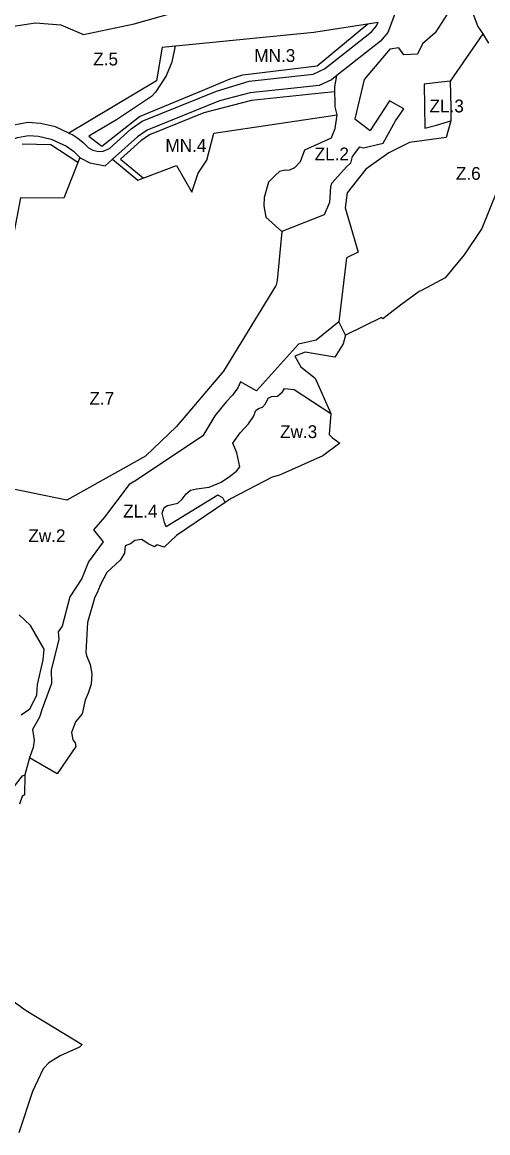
# Model space of a CAD drawing. Extents: x 7425478 to 7427982, y 5538517 to 5541171.
# Drawn here: x 7426780 to 7427144, y 5539848 to 5540715 of the extents above; entities that cross this region are included whole.
import ezdxf

# ---------------------------------------------------------------- set-up
doc = ezdxf.new("R2010")
doc.units = 0
for name, color, linetype in [('linie_rozgraniczajace', 7, 'Continuous'), ('linie_zabudowy_nieprzekraczalne', 7, 'Continuous'), ('oznaczenia_przeznaczen', 7, 'Continuous')]:
    doc.layers.add(name, color=color, linetype=linetype)

msp = doc.modelspace()

# ---------------------------------------------------------------- linework, layer by layer
at = {"layer": 'linie_rozgraniczajace'}
for p, q in [((7427139.8, 5540706.06), (7427114.35, 5540669.29)), ((7426885.22, 5540669.48), (7426816.94, 5540628.58)), ((7426929.93, 5540628.75), (7427026.21, 5540642.98)), ((7426924.55, 5540607.43), (7426929.93, 5540628.75)), ((7426850.92, 5540608.27), (7426845.13, 5540603.14)), ((7426850.92, 5540608.27), (7426870.65, 5540592.04)), ((7426870.65, 5540592.04), (7426900.74, 5540603.34)), ((7427032.6, 5540471.1), (7427027.43, 5540481.44))]:
    msp.add_line(p, q, dxfattribs=at)
for points in [[(7427158.39, 5540798), (7427136.34, 5540789.37), (7427139.67, 5540778.67), (7427134.83, 5540763.31), (7427130.62, 5540745.07), (7427123.48, 5540740.52), (7427119.13, 5540731.95), (7427130.46, 5540726.07), (7427136.02, 5540711.98), (7427139.8, 5540706.06), (7427144.31, 5540698.99)], [(7426717.2, 5540708.68), (7426751.28, 5540708.68), (7426790.92, 5540714.76), (7426810.72, 5540713.06), (7426828.41, 5540705.75), (7426867.84, 5540713.85), (7426908.44, 5540725.51), (7426925.27, 5540731.18), (7426935.28, 5540732.24), (7426974.9, 5540738.42), (7427001.7, 5540742.96), (7427027.17, 5540753.71), (7427042.19, 5540761.09), (7427056.12, 5540769.24), (7427073.04, 5540767.39)], [(7427083.04, 5540766.57), (7427080.34, 5540749.86), (7427070.28, 5540719), (7427065.65, 5540707.16), (7427060.1, 5540700.5), (7427027.21, 5540674.65), (7427025.96, 5540673.63)], [(7427119.13, 5540731.95), (7427118.93, 5540725.92), (7427111.93, 5540721.58), (7427102.54, 5540707.01), (7427092.86, 5540698.44), (7427088.98, 5540690.18), (7427078.3, 5540689.89), (7427074.37, 5540695.25), (7427067.2, 5540694.18), (7427047.31, 5540670.39), (7427040.04, 5540639.71), (7427051.91, 5540630.81)], [(7426816.94, 5540628.58), (7426819.88, 5540627.22), (7426823.81, 5540624.73), (7426827.92, 5540621.26), (7426832.12, 5540617.13), (7426835.64, 5540615.25), (7426839.95, 5540614.22), (7426843.52, 5540614.54), (7426848.64, 5540616.78), (7426865.59, 5540631.91), (7426874, 5540638.01), (7426932, 5540661.5), (7426957.66, 5540669.31), (7427007.45, 5540674.6), (7427016.45, 5540678.79), (7427020.96, 5540682.46), (7427053.09, 5540707.71), (7427056.93, 5540712.31), (7427058.07, 5540715.23)], [(7426889.78, 5540695.66), (7427007.88, 5540707.42), (7427058.07, 5540715.23)], [(7426889.78, 5540695.66), (7426885.22, 5540669.48)], [(7427025.96, 5540673.63), (7427021.8, 5540670.25), (7427012.12, 5540665.74), (7426958.39, 5540660.04), (7426934.51, 5540653.88), (7426877.87, 5540630.95), (7426870.53, 5540625.74), (7426850.92, 5540608.27)], [(7427026.21, 5540642.98), (7427024.52, 5540649.27), (7427024.51, 5540664.71), (7427025.96, 5540673.63)], [(7427114.35, 5540669.29), (7427102.63, 5540667.82), (7427094.19, 5540666.76), (7427094.51, 5540632.57), (7427103.73, 5540634.94), (7427114.78, 5540638.2)], [(7427114.35, 5540669.29), (7427114.9, 5540648.8), (7427114.78, 5540638.2)], [(7427043.54, 5540617.89), (7427046.67, 5540617.1), (7427062.21, 5540620.8), (7427071.76, 5540638.27), (7427078.24, 5540647.6), (7427067.16, 5540653.8), (7427051.91, 5540630.81)], [(7427022.1, 5540625.69), (7427024.7, 5540632.23), (7427026.21, 5540642.98)], [(7427114.78, 5540638.2), (7427111.29, 5540625.32), (7427082.64, 5540621.43), (7427066.46, 5540613.16), (7427048.55, 5540600.64), (7427033.93, 5540581.97), (7427032.56, 5540570.47), (7427042.54, 5540535.68), (7427033.51, 5540531.31), (7427027.43, 5540481.44)], [(7426816.94, 5540628.58), (7426806.42, 5540633.45), (7426794.75, 5540636.3), (7426784.82, 5540636.93), (7426773.93, 5540634.87), (7426749.1, 5540625.08), (7426736.88, 5540615.14)], [(7426539.11, 5540398.25), (7426541.43, 5540399.68), (7426607.94, 5540440.48), (7426649.9, 5540466.22), (7426659.15, 5540471.89), (7426732.05, 5540546.65), (7426737.1, 5540553.97), (7426740.18, 5540562.9), (7426745.32, 5540603.54), (7426750.19, 5540612.79), (7426754.12, 5540616.34), (7426776.71, 5540625.22), (7426785.4, 5540626.76), (7426793.22, 5540626.29), (7426803.14, 5540623.95), (7426814.99, 5540618.47), (7426820.42, 5540614.61), (7426825.48, 5540609.63)], [(7426985.66, 5540599.77), (7426989.18, 5540600.1), (7426993.13, 5540601.91), (7426997.47, 5540606.59), (7427001.04, 5540615.75), (7427021.81, 5540624.97), (7427022.1, 5540625.69)], [(7427043.54, 5540617.89), (7427038, 5540610.44), (7427036.59, 5540605.3), (7427033.74, 5540602.71), (7427021.87, 5540589.27), (7427020.93, 5540586.74), (7427020.23, 5540574.54), (7427015.95, 5540565), (7426983.04, 5540551.77)], [(7426825.48, 5540609.63), (7426812.98, 5540577.96), (7426779.26, 5540578.26), (7426773.48, 5540547.95), (7426764.01, 5540550.84), (7426743.97, 5540499.31)], [(7426825.48, 5540609.63), (7426826.1, 5540609.01), (7426833.3, 5540605.53), (7426845.13, 5540603.14)], [(7426900.74, 5540603.34), (7426912.69, 5540582.71), (7426917.78, 5540597.51), (7426924.55, 5540607.43)], [(7426985.66, 5540599.77), (7426981.3, 5540598.7), (7426977.71, 5540595.7), (7426972.69, 5540590.28), (7426969.22, 5540578.33), (7426969.01, 5540572.04), (7426970.63, 5540563.16), (7426983.04, 5540551.77)], [(7427150.95, 5540583.84), (7427138.96, 5540554.17), (7427125.36, 5540533.58), (7427110.38, 5540515.76), (7427091.99, 5540505.94), (7427090.1, 5540504.94), (7427075.65, 5540494.42), (7427061.83, 5540483.7), (7427060.76, 5540484.77), (7427032.6, 5540471.1), (7427030.76, 5540464.33), (7427024.38, 5540453.77), (7427001.36, 5540457.81), (7426993.3, 5540454.47), (7426997.77, 5540446.18), (7427009.07, 5540437.32), (7427021.32, 5540409.86), (7427020.08, 5540393.37), (7427022.61, 5540390.72), (7427028.34, 5540386.75), (7427015.04, 5540376.71), (7426981.24, 5540361.71), (7426975.61, 5540360.24), (7426943.45, 5540343.38), (7426938.89, 5540340.31), (7426900.87, 5540314.74), (7426891.34, 5540305.49), (7426885.84, 5540307.32), (7426883.78, 5540305.87), (7426878.7, 5540308.24), (7426876.09, 5540309.93), (7426873.47, 5540311.61), (7426868.35, 5540310.69), (7426864.88, 5540308.01), (7426860.83, 5540306.48), (7426860.3, 5540300.95), (7426858.62, 5540298.27), (7426857.01, 5540295.41), (7426846.5, 5540285.63), (7426841.75, 5540276.81), (7426839.37, 5540271.25), (7426836.99, 5540265.69), (7426831.46, 5540246.75), (7426830.08, 5540223.37), (7426830.71, 5540220.99), (7426833.37, 5540213.93), (7426834.71, 5540206.55), (7426834.36, 5540198.53), (7426831.92, 5540191.52), (7426829.64, 5540186.14), (7426827.16, 5540175.36), (7426822.14, 5540169.32), (7426818.84, 5540160.81), (7426819.93, 5540155.13), (7426821.9, 5540152.81), (7426822.39, 5540149.98), (7426807.77, 5540128.74), (7426786.11, 5540141.2), (7426782.46, 5540127.73), (7426782.23, 5540112.34), (7426780.53, 5540110.98), (7426778.31, 5540104.9)], [(7426983.04, 5540551.77), (7426979.38, 5540513.58), (7426978.32, 5540509.52)], [(7426978.32, 5540509.52), (7426978.15, 5540509.1), (7426937.58, 5540442.83), (7426900.97, 5540399.74), (7426876.56, 5540376.66)], [(7427027.43, 5540481.44), (7427009.75, 5540467.1), (7426996.15, 5540464.02), (7426963.33, 5540427.58), (7426950.77, 5540434.53), (7426948.61, 5540429.76), (7426944.61, 5540424.21), (7426939.52, 5540418.88), (7426930.86, 5540407.97), (7426921.46, 5540392.4), (7426869.62, 5540357.86), (7426863.82, 5540354.4), (7426844.64, 5540328.87), (7426836.17, 5540319.03), (7426843.63, 5540309.7), (7426832.11, 5540294.14), (7426827.07, 5540280.94), (7426817.51, 5540266.74), (7426811.68, 5540243.98), (7426808.47, 5540239.34), (7426808.92, 5540233.63), (7426803.14, 5540209.55), (7426803.27, 5540199.17), (7426796, 5540179.23), (7426794.02, 5540172.87), (7426788.54, 5540163.16), (7426789.86, 5540154.88), (7426789.06, 5540149.13), (7426786.11, 5540141.2)], [(7426938.89, 5540340.31), (7426937.09, 5540344.03), (7426933.01, 5540346), (7426892.91, 5540321.35), (7426891.45, 5540324.65), (7426889.79, 5540332.1), (7426891.19, 5540336.41), (7426893.71, 5540337.94), (7426901.86, 5540339.76), (7426905.37, 5540342.93), (7426908.35, 5540347.13), (7426911.75, 5540350.1), (7426916.53, 5540351.01), (7426926.41, 5540352.22), (7426935.65, 5540356.31), (7426942.22, 5540360.57), (7426947.79, 5540364.77), (7426950.29, 5540368.32), (7426947.95, 5540379.04), (7426944.74, 5540386.58), (7426950.54, 5540394.76), (7426957.02, 5540401.74), (7426960.85, 5540407.56), (7426962.76, 5540412.3), (7426964.81, 5540413.63), (7426967.9, 5540414.8), (7426970.32, 5540417.26), (7426972.49, 5540421.74), (7426974.94, 5540423.09), (7426979.74, 5540423.33), (7426983.6, 5540426.75), (7426985.06, 5540429.39), (7426992.55, 5540428.67), (7427021.32, 5540409.86)], [(7426876.56, 5540376.66), (7426815.24, 5540342.11), (7426759.33, 5540353.52), (7426712.55, 5540353.68), (7426701.1, 5540359.93), (7426698.75, 5540367.01), (7426655.83, 5540367.75), (7426652.37, 5540366.73), (7426608.69, 5540358.29), (7426595.99, 5540354.73), (7426574.58, 5540344.68), (7426528.94, 5540317.84), (7426509.87, 5540298.47), (7426478.31, 5540275.12)], [(7426779.66, 5540174.68), (7426786.36, 5540179.24), (7426791.77, 5540190.07), (7426792.35, 5540198.35), (7426796.85, 5540217.51), (7426797.67, 5540225.83), (7426786.93, 5540244.43), (7426778.12, 5540252.72)], [(7426746.25, 5540083.73), (7426738.37, 5540095.96), (7426747.68, 5540103.35), (7426755.24, 5540103.81), (7426764.91, 5540109.86), (7426770.52, 5540116.42), (7426775.13, 5540120.09), (7426780.59, 5540127.08), (7426782.46, 5540127.73)], [(7426758.36, 5539961.98), (7426783.48, 5539943.79), (7426827.32, 5539917.3), (7426825.27, 5539915.32), (7426809.97, 5539908.4), (7426801.25, 5539903.11), (7426796.73, 5539898.35), (7426788.38, 5539880.66), (7426777.89, 5539848.46)]]:
    msp.add_lwpolyline(points, dxfattribs=at)
at = {"layer": 'linie_zabudowy_nieprzekraczalne'}
msp.add_line((7426857.07, 5540608.36), (7426874.91, 5540593.71), dxfattribs=at)
for points in [[(7427010.57, 5540681.28), (7427050.02, 5540713.97)], [(7426899.94, 5540696.67), (7426897.3, 5540684.13), (7426892.7, 5540673.3), (7426884.54, 5540660.66), (7426881.34, 5540657.32), (7426854.04, 5540639.06), (7426838.23, 5540629.67), (7426832.41, 5540626.22)], [(7426942.67, 5540671), (7426952.66, 5540674.28), (7427010.57, 5540681.28)], [(7426832.41, 5540626.22), (7426842.52, 5540618.46), (7426872.05, 5540641.53), (7426918.64, 5540661.01), (7426942.67, 5540671)], [(7427024.51, 5540660.99), (7427013.75, 5540659.88), (7426959.46, 5540654.12), (7426922.26, 5540644.56), (7426879.8, 5540627.41), (7426873.03, 5540622.61), (7426857.07, 5540608.36)], [(7426823.93, 5540605.71), (7426802.89, 5540619.51), (7426780.48, 5540620.13)]]:
    msp.add_lwpolyline(points, dxfattribs=at)

# ---------------------------------------------------------------- texts
at = {"layer": 'oznaczenia_przeznaczen'}
for s, p in [('Z.5', (7426835.9, 5540681.46)), ('MN.3', (7426961.58, 5540684.24)), ('ZL.3', (7427098.27, 5540644.84)), ('MN.4', (7426892.2, 5540614.06)), ('ZL.2', (7427008.63, 5540607.44)), ('Z.6', (7427118.86, 5540592.21)), ('Z.7', (7426832.92, 5540416.62)), ('Zw.3', (7426981.67, 5540390.67)), ('ZL.4', (7426859.23, 5540328.63)), ('Zw.2', (7426785.26, 5540309.44))]:
    msp.add_text(s, height=10, dxfattribs=at).set_placement(p)

doc.saveas('drawing.dxf')
